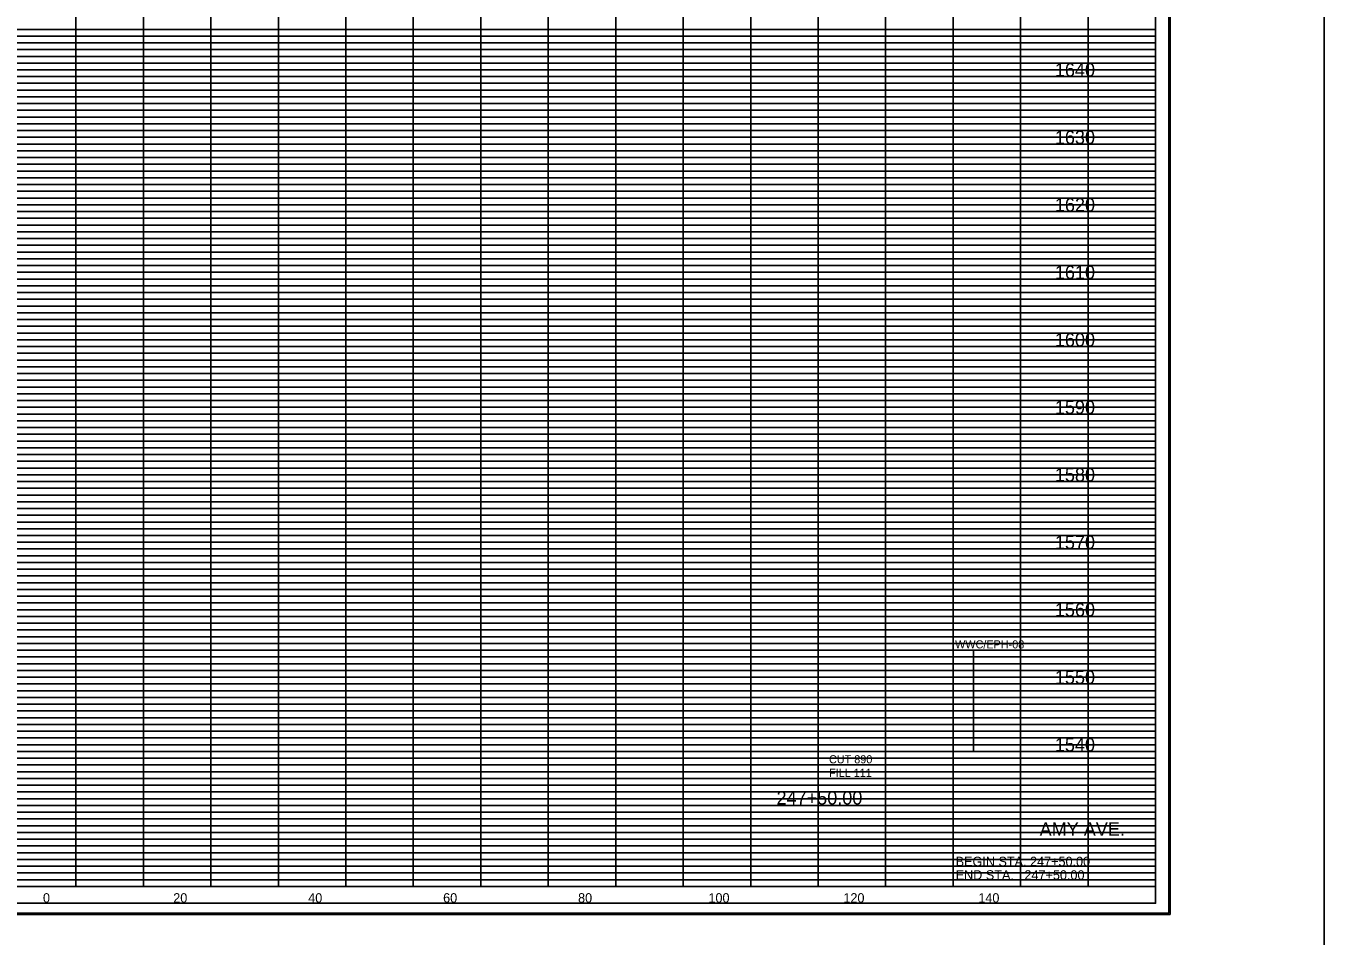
# Model space of a CAD drawing. Extents: x 955 to 1375, y 1248 to 3657.
# Drawn here: x 1152.6 to 1345, y 2342.7 to 2477.5 of the extents above; entities that cross this region are included whole.
import ezdxf

# ---------------------------------------------------------------- set-up
doc = ezdxf.new("R2010")
doc.units = 0
for name, color, linetype in [('DESIGN - SHEET - Corner Text', 7, 'Continuous'), ('DESIGN - SHEET - Light Grid', 7, 'Continuous'), ('DESIGN - SHEET - Linework', 7, 'Continuous'), ('DESIGN - SHEET - Plot Shape', 7, 'Continuous'), ('DESIGN - TYPICAL - Text', 7, 'Continuous'), ('DESIGN - UTILITIES - Cable (Overhead) with Text', 7, 'Continuous'), ('SURVEY - NON-TRANSPORTATION - Features', 7, 'Continuous'), ('SURVEY - NON-TRANSPORTATION - Features Text', 7, 'Continuous')]:
    doc.layers.add(name, color=color, linetype=linetype)

# ---------------------------------------------------------------- blocks, each defined once
blk = doc.blocks.new('XSTSHT')
at = {"layer": 'DESIGN - SHEET - Light Grid'}
for p, q in [((8, 12.7), (16, 12.7)), ((16, 12.7), (24, 12.7)), ((24, 12.7), (32, 12.7)), ((8, 12.6), (16, 12.6)), ((16, 12.6), (24, 12.6)), ((24, 12.6), (32, 12.6)), ((8, 12.5), (16, 12.5)), ((8, 12.4), (16, 12.4)), ((16, 12.5), (24, 12.5)), ((16, 12.4), (24, 12.4)), ((24, 12.5), (32, 12.5)), ((24, 12.4), (32, 12.4)), ((8, 12.3), (16, 12.3)), ((8, 12.2), (16, 12.2)), ((16, 12.3), (24, 12.3)), ((16, 12.2), (24, 12.2)), ((24, 12.3), (32, 12.3)), ((24, 12.2), (32, 12.2)), ((8, 12.1), (16, 12.1)), ((16, 12.1), (24, 12.1)), ((24, 12.1), (32, 12.1)), ((8, 11.9), (16, 11.9)), ((8, 11.8), (16, 11.8)), ((16, 11.9), (24, 11.9)), ((16, 11.8), (24, 11.8)), ((24, 11.9), (32, 11.9)), ((24, 11.8), (32, 11.8)), ((8, 11.7), (16, 11.7)), ((8, 11.6), (16, 11.6)), ((16, 11.7), (24, 11.7)), ((16, 11.6), (24, 11.6)), ((24, 11.7), (32, 11.7)), ((24, 11.6), (32, 11.6)), ((8, 11.5), (16, 11.5)), ((8, 11.4), (16, 11.4)), ((16, 11.5), (24, 11.5)), ((16, 11.4), (24, 11.4)), ((24, 11.5), (32, 11.5)), ((24, 11.4), (32, 11.4)), ((8, 11.3), (16, 11.3)), ((8, 11.2), (16, 11.2)), ((16, 11.3), (24, 11.3)), ((16, 11.2), (24, 11.2)), ((24, 11.3), (32, 11.3)), ((24, 11.2), (32, 11.2)), ((8, 11.1), (16, 11.1)), ((16, 11.1), (24, 11.1)), ((24, 11.1), (32, 11.1)), ((8, 10.9), (16, 10.9)), ((8, 10.8), (16, 10.8)), ((16, 10.9), (24, 10.9)), ((16, 10.8), (24, 10.8)), ((24, 10.9), (32, 10.9)), ((24, 10.8), (32, 10.8)), ((8, 10.7), (16, 10.7)), ((8, 10.6), (16, 10.6)), ((16, 10.7), (24, 10.7)), ((16, 10.6), (24, 10.6)), ((24, 10.7), (32, 10.7)), ((24, 10.6), (32, 10.6)), ((8, 10.5), (16, 10.5)), ((8, 10.4), (16, 10.4)), ((16, 10.5), (24, 10.5)), ((16, 10.4), (24, 10.4)), ((24, 10.5), (32, 10.5)), ((24, 10.4), (32, 10.4)), ((8, 10.3), (16, 10.3)), ((8, 10.2), (16, 10.2)), ((16, 10.3), (24, 10.3)), ((16, 10.2), (24, 10.2)), ((24, 10.3), (32, 10.3)), ((24, 10.2), (32, 10.2)), ((8, 10.1), (16, 10.1)), ((16, 10.1), (24, 10.1)), ((24, 10.1), (32, 10.1)), ((8, 9.9), (16, 9.9)), ((16, 9.9), (24, 9.9)), ((24, 9.9), (32, 9.9)), ((8, 9.8), (16, 9.8)), ((8, 9.7), (16, 9.7)), ((16, 9.8), (24, 9.8)), ((16, 9.7), (24, 9.7)), ((24, 9.8), (32, 9.8)), ((24, 9.7), (32, 9.7)), ((8, 9.6), (16, 9.6)), ((8, 9.5), (16, 9.5)), ((16, 9.6), (24, 9.6)), ((16, 9.5), (24, 9.5)), ((24, 9.6), (32, 9.6)), ((24, 9.5), (32, 9.5)), ((8, 9.4), (16, 9.4)), ((8, 9.3), (16, 9.3)), ((16, 9.4), (24, 9.4)), ((16, 9.3), (24, 9.3)), ((24, 9.4), (32, 9.4)), ((24, 9.3), (32, 9.3)), ((8, 9.2), (16, 9.2)), ((8, 9.1), (16, 9.1)), ((16, 9.2), (24, 9.2)), ((16, 9.1), (24, 9.1)), ((24, 9.2), (32, 9.2)), ((24, 9.1), (32, 9.1)), ((8, 8.9), (16, 8.9)), ((16, 8.9), (24, 8.9)), ((24, 8.9), (32, 8.9)), ((8, 8.8), (16, 8.8)), ((8, 8.7), (16, 8.7)), ((16, 8.8), (24, 8.8)), ((16, 8.7), (24, 8.7)), ((24, 8.8), (32, 8.8)), ((24, 8.7), (32, 8.7)), ((8, 8.6), (16, 8.6)), ((8, 8.5), (16, 8.5)), ((16, 8.6), (24, 8.6)), ((16, 8.5), (24, 8.5)), ((24, 8.6), (32, 8.6)), ((24, 8.5), (32, 8.5)), ((8, 8.4), (16, 8.4)), ((8, 8.3), (16, 8.3)), ((16, 8.4), (24, 8.4)), ((16, 8.3), (24, 8.3)), ((24, 8.4), (32, 8.4)), ((24, 8.3), (32, 8.3)), ((8, 8.2), (16, 8.2)), ((8, 8.1), (16, 8.1)), ((16, 8.2), (24, 8.2)), ((16, 8.1), (24, 8.1)), ((24, 8.2), (32, 8.2)), ((24, 8.1), (32, 8.1)), ((8, 7.9), (16, 7.9)), ((16, 7.9), (24, 7.9)), ((24, 7.9), (32, 7.9)), ((8, 7.8), (16, 7.8)), ((8, 7.7), (16, 7.7)), ((16, 7.8), (24, 7.8)), ((16, 7.7), (24, 7.7)), ((24, 7.8), (32, 7.8)), ((24, 7.7), (32, 7.7)), ((8, 7.6), (16, 7.6)), ((16, 7.6), (24, 7.6)), ((24, 7.6), (32, 7.6)), ((8, 7.5), (16, 7.5)), ((8, 7.4), (16, 7.4)), ((16, 7.5), (24, 7.5)), ((16, 7.4), (24, 7.4)), ((24, 7.5), (32, 7.5)), ((24, 7.4), (32, 7.4)), ((8, 7.3), (16, 7.3)), ((8, 7.2), (16, 7.2)), ((16, 7.3), (24, 7.3)), ((16, 7.2), (24, 7.2)), ((24, 7.3), (32, 7.3)), ((24, 7.2), (32, 7.2)), ((8, 7.1), (16, 7.1)), ((16, 7.1), (24, 7.1)), ((24, 7.1), (32, 7.1)), ((8, 6.9), (16, 6.9)), ((8, 6.8), (16, 6.8)), ((16, 6.9), (24, 6.9)), ((16, 6.8), (24, 6.8)), ((24, 6.9), (32, 6.9)), ((24, 6.8), (32, 6.8)), ((8, 6.7), (16, 6.7)), ((8, 6.6), (16, 6.6)), ((16, 6.7), (24, 6.7)), ((16, 6.6), (24, 6.6)), ((24, 6.7), (32, 6.7)), ((24, 6.6), (32, 6.6)), ((8, 6.5), (16, 6.5)), ((8, 6.4), (16, 6.4)), ((16, 6.5), (24, 6.5)), ((16, 6.4), (24, 6.4)), ((24, 6.5), (32, 6.5)), ((24, 6.4), (32, 6.4)), ((8, 6.3), (16, 6.3)), ((8, 6.2), (16, 6.2)), ((16, 6.3), (24, 6.3)), ((16, 6.2), (24, 6.2)), ((24, 6.3), (32, 6.3)), ((24, 6.2), (32, 6.2)), ((8, 6.1), (16, 6.1)), ((16, 6.1), (24, 6.1)), ((24, 6.1), (32, 6.1)), ((8, 5.9), (16, 5.9)), ((8, 5.8), (16, 5.8)), ((16, 5.9), (24, 5.9)), ((16, 5.8), (24, 5.8)), ((24, 5.9), (32, 5.9)), ((24, 5.8), (32, 5.8)), ((8, 5.7), (16, 5.7)), ((8, 5.6), (16, 5.6)), ((16, 5.7), (24, 5.7)), ((16, 5.6), (24, 5.6)), ((24, 5.7), (32, 5.7)), ((24, 5.6), (32, 5.6)), ((8, 5.5), (16, 5.5)), ((8, 5.4), (16, 5.4)), ((16, 5.5), (24, 5.5)), ((16, 5.4), (24, 5.4)), ((24, 5.5), (32, 5.5)), ((24, 5.4), (32, 5.4)), ((8, 5.3), (16, 5.3)), ((8, 5.2), (16, 5.2)), ((16, 5.3), (24, 5.3)), ((16, 5.2), (24, 5.2)), ((24, 5.3), (32, 5.3)), ((24, 5.2), (32, 5.2)), ((8, 5.1), (16, 5.1)), ((16, 5.1), (24, 5.1)), ((24, 5.1), (32, 5.1)), ((8, 4.9), (16, 4.9)), ((16, 4.9), (24, 4.9)), ((24, 4.9), (32, 4.9)), ((8, 4.8), (16, 4.8)), ((8, 4.7), (16, 4.7)), ((16, 4.8), (24, 4.8)), ((16, 4.7), (24, 4.7)), ((24, 4.8), (32, 4.8)), ((24, 4.7), (32, 4.7)), ((8, 4.6), (16, 4.6)), ((8, 4.5), (16, 4.5)), ((16, 4.6), (24, 4.6)), ((16, 4.5), (24, 4.5)), ((24, 4.6), (32, 4.6)), ((24, 4.5), (32, 4.5)), ((8, 4.4), (16, 4.4)), ((8, 4.3), (16, 4.3)), ((16, 4.4), (24, 4.4)), ((16, 4.3), (24, 4.3)), ((24, 4.4), (32, 4.4)), ((24, 4.3), (32, 4.3)), ((8, 4.2), (16, 4.2)), ((8, 4.1), (16, 4.1)), ((16, 4.2), (24, 4.2)), ((16, 4.1), (24, 4.1)), ((24, 4.2), (32, 4.2)), ((24, 4.1), (32, 4.1)), ((8, 3.9), (16, 3.9)), ((16, 3.9), (24, 3.9)), ((24, 3.9), (32, 3.9)), ((8, 3.8), (16, 3.8)), ((8, 3.7), (16, 3.7)), ((16, 3.8), (24, 3.8)), ((16, 3.7), (24, 3.7)), ((24, 3.8), (32, 3.8)), ((24, 3.7), (32, 3.7)), ((8, 3.6), (16, 3.6)), ((8, 3.5), (16, 3.5)), ((16, 3.6), (24, 3.6)), ((16, 3.5), (24, 3.5)), ((24, 3.6), (32, 3.6)), ((24, 3.5), (32, 3.5)), ((8, 3.4), (16, 3.4)), ((8, 3.3), (16, 3.3)), ((16, 3.4), (24, 3.4)), ((16, 3.3), (24, 3.3)), ((24, 3.4), (32, 3.4)), ((24, 3.3), (32, 3.3)), ((8, 3.2), (16, 3.2)), ((8, 3.1), (16, 3.1)), ((16, 3.2), (24, 3.2)), ((16, 3.1), (24, 3.1)), ((24, 3.2), (32, 3.2)), ((24, 3.1), (32, 3.1)), ((8, 2.9), (16, 2.9)), ((16, 2.9), (24, 2.9)), ((24, 2.9), (32, 2.9)), ((8, 2.8), (16, 2.8)), ((8, 2.7), (16, 2.7)), ((16, 2.8), (24, 2.8)), ((16, 2.7), (24, 2.7)), ((24, 2.8), (32, 2.8)), ((24, 2.7), (32, 2.7)), ((8, 2.6), (16, 2.6)), ((16, 2.6), (24, 2.6)), ((24, 2.6), (32, 2.6)), ((8, 2.5), (16, 2.5)), ((8, 2.4), (16, 2.4)), ((16, 2.5), (24, 2.5)), ((16, 2.4), (24, 2.4)), ((24, 2.5), (32, 2.5)), ((24, 2.4), (32, 2.4)), ((8, 2.3), (16, 2.3)), ((8, 2.2), (16, 2.2)), ((16, 2.3), (24, 2.3)), ((16, 2.2), (24, 2.2)), ((24, 2.3), (32, 2.3)), ((24, 2.2), (32, 2.2)), ((8, 2.1), (16, 2.1)), ((16, 2.1), (24, 2.1)), ((24, 2.1), (32, 2.1)), ((8, 1.9), (16, 1.9)), ((8, 1.8), (16, 1.8)), ((16, 1.9), (24, 1.9)), ((16, 1.8), (24, 1.8)), ((24, 1.9), (32, 1.9)), ((24, 1.8), (32, 1.8)), ((8, 1.7), (16, 1.7)), ((8, 1.6), (16, 1.6)), ((16, 1.7), (24, 1.7)), ((16, 1.6), (24, 1.6)), ((24, 1.7), (32, 1.7)), ((24, 1.6), (32, 1.6)), ((8, 1.5), (16, 1.5)), ((8, 1.4), (16, 1.4)), ((16, 1.5), (24, 1.5)), ((16, 1.4), (24, 1.4)), ((24, 1.5), (32, 1.5)), ((24, 1.4), (32, 1.4)), ((8, 1.3), (16, 1.3)), ((8, 1.2), (16, 1.2)), ((16, 1.3), (24, 1.3)), ((16, 1.2), (24, 1.2)), ((24, 1.3), (32, 1.3)), ((24, 1.2), (32, 1.2)), ((8, 1.1), (16, 1.1)), ((16, 1.1), (24, 1.1)), ((24, 1.1), (32, 1.1)), ((8, 0.9), (16, 0.9)), ((8, 0.8), (16, 0.8)), ((16, 0.9), (24, 0.9)), ((16, 0.8), (24, 0.8)), ((24, 0.9), (32, 0.9)), ((24, 0.8), (32, 0.8)), ((8, 0.7), (16, 0.7)), ((8, 0.6), (16, 0.6)), ((16, 0.7), (24, 0.7)), ((16, 0.6), (24, 0.6)), ((24, 0.7), (32, 0.7)), ((24, 0.6), (32, 0.6)), ((8, 0.5), (16, 0.5)), ((8, 0.4), (16, 0.4)), ((16, 0.5), (24, 0.5)), ((16, 0.4), (24, 0.4)), ((24, 0.5), (32, 0.5)), ((24, 0.4), (32, 0.4)), ((8, 0.3), (16, 0.3)), ((8, 0.2), (16, 0.2)), ((16, 0.3), (24, 0.3)), ((16, 0.2), (24, 0.2)), ((24, 0.3), (32, 0.3)), ((24, 0.2), (32, 0.2)), ((8, 0.1), (16, 0.1)), ((16, 0.1), (24, 0.1)), ((24, 0.1), (32, 0.1))]:
    blk.add_line(p, q, dxfattribs=at)
at = {"layer": 'DESIGN - SHEET - Linework'}
for p, q in [((32.217, 21.414), (32.217, -0.414)), ((16, 0), (16, 21)), ((17, 0), (17, 21)), ((18, 0), (18, 21)), ((19, 0), (19, 21)), ((20, 0), (20, 21)), ((21, 0), (21, 21)), ((22, 0), (22, 21)), ((23, 0), (23, 21)), ((24, 0), (24, 21)), ((25, 0), (25, 21)), ((26, 0), (26, 21)), ((27, 0), (27, 21)), ((28, 0), (28, 20)), ((29, 0), (29, 20)), ((30, 0), (30, 20)), ((31, 0), (31, 20)), ((0, 12), (32, 12)), ((0, 11), (32, 11)), ((0, 10), (32, 10)), ((0, 9), (32, 9)), ((0, 8), (32, 8)), ((0, 7), (32, 7)), ((0, 6), (32, 6)), ((0, 5), (32, 5)), ((0, 4), (32, 4)), ((0, 3), (32, 3)), ((0, 2), (32, 2)), ((0, 1), (32, 1)), ((-1.823, -0.414), (32.217, -0.414))]:
    blk.add_line(p, q, dxfattribs=at)
blk.add_lwpolyline([(0, 21), (0, 0), (32, 0), (32, 21), (0, 21)], dxfattribs=at)
at = {"layer": 'DESIGN - SHEET - Plot Shape'}
for points in [[(-1.803, 21.394), (32.197, 21.394), (32.197, -0.394), (-1.803, -0.394)], [(-0.85, 21), (32, 21), (32, -0.25), (-0.85, -0.25)]]:
    blk.add_lwpolyline(points, close=True, dxfattribs=at)

msp = doc.modelspace()

# ---------------------------------------------------------------- linework, layer by layer
at = {"layer": 'DESIGN - SHEET - Plot Shape'}
msp.add_lwpolyline([(991.5, 2347.5), (1320, 2347.5), (1320, 2560), (991.5, 2560)], close=True, dxfattribs=at)
at = {"layer": 'SURVEY - NON-TRANSPORTATION - Features'}
msp.add_line((1293.01, 2369.91), (1293.01, 2384.91), dxfattribs=at)
at = {"layer": 'SURVEY - NON-TRANSPORTATION - Features Text'}
msp.add_lwpolyline([(955.41, 1505.76), (1344.98, 1505.76), (1344.98, 3398.01), (955.41, 3398.01)], close=True, dxfattribs=at)

# ---------------------------------------------------------------- block references
at = {"layer": 'DESIGN - UTILITIES - Cable (Overhead) with Text', "xscale": 10, "yscale": 10}
msp.add_blockref('XSTSHT', (1000, 2350), dxfattribs=at)

# ---------------------------------------------------------------- texts
at = {"layer": 'DESIGN - SHEET - Corner Text'}
for s, height, p in [('AMY AVE.', 2, (1302.83, 2357.5)), ('BEGIN STA. 247+50.00', 1.4, (1290.38, 2353)), ('END STA.   247+50.00', 1.4, (1290.38, 2351))]:
    msp.add_text(s, height=height, dxfattribs=at).set_placement(p)
at = {"layer": 'DESIGN - TYPICAL - Text'}
for s, height, p in [('     1640     ', 2, (1301.37, 2470)), ('     1630     ', 2, (1301.37, 2460)), ('     1620     ', 2, (1301.37, 2450)), ('     1610     ', 2, (1301.37, 2440)), ('     1600     ', 2, (1301.37, 2430)), ('     1590     ', 2, (1301.37, 2420)), ('     1580     ', 2, (1301.37, 2410)), ('     1570     ', 2, (1301.37, 2400)), ('     1560     ', 2, (1301.37, 2390)), ('     1550     ', 2, (1301.37, 2380)), ('     1540     ', 2, (1301.37, 2370)), ('CUT 890', 1.2, (1271.61, 2368.24)), ('FILL 111', 1.2, (1271.61, 2366.24)), ('     247+50.00     ', 2, (1260.12, 2362.13)), ('     0     ', 1.4, (1152.51, 2347.6)), ('     0     ', 1.4, (1152.51, 2347.6)), ('     20     ', 1.4, (1171.82, 2347.6)), ('     40     ', 1.4, (1191.82, 2347.6)), ('     60     ', 1.4, (1211.82, 2347.6)), ('     80     ', 1.4, (1231.82, 2347.6)), ('     100     ', 1.4, (1251.14, 2347.6)), ('     120     ', 1.4, (1271.14, 2347.6)), ('     140     ', 1.4, (1291.14, 2347.6))]:
    msp.add_text(s, height=height, dxfattribs=at).set_placement(p)
at = {"layer": 'SURVEY - NON-TRANSPORTATION - Features'}
msp.add_text('WWC/EPH-08', height=1.2, dxfattribs=at).set_placement((1290.3, 2385.27))

doc.saveas('drawing.dxf')
